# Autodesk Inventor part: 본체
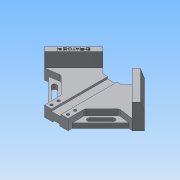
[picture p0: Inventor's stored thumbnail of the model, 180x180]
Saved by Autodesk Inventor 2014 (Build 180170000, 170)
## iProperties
Created: 2020-05
Part Number: 본체
Material: 알루미늄 6061
Document SubType Name: Modeling
Designer: net
Density: 2.71 g/cm^3
Appearance: 알루미늄 - 평지
Mass: 579.76 g
Surface Area: 409.973 cm^2
Volume: 213.934 cm^3
Author: net
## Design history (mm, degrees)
sketch "스케치1"
  geometry: L1 (0, 84.853)-(-84.853, 0); L2 (-84.853, 0)-(0, -84.853); L3 (0, -84.853)-(84.853, 0); L4 (84.853, 0)-(0, 84.853); L5 (-84.853, 0)-(84.853, 0); L6 (-35.355, 49.497)-(-16.005, 30.147); L7 (-16.005, 30.147)-(16.005, 30.147); L8 (16.005, 30.147)-(35.355, 49.497); L9 (0, 84.853)-(0, -84.853); L10 (-20, -64.853)-(20, -64.853); L11 (-6, 30.147)-(-6, -64.853); L12 (6, 30.147)-(6, -64.853); L13 (24.749, 38.891)-(74.246, -10.607); L14 (-24.749, 38.891)-(-74.246, -10.607); 3 further points
  constraints: 28 end point, 12 point on line, 10 perpendicular, 2 coincident, 2 parallel, 1 horizontal, 1 horizontal alignment, 1 midpoint, 1 vertical alignment
  dimensions: "d6" = 120 distance of L3.end L1.start; "d7" = 120 distance of L2.end L3.end (derived); "d9" = 50 distance of L1.start L6.start; "d10" = 50 distance of L8.end L1.start; "d11" = 20 distance from line of L2.end L10; "d13" = 12 distance between parallel lines of L12 L11; "d14" = 6 distance from line of L12 point (0, 0); "d15" = 15 distance between parallel lines of L4 L13; "d16" = 15 distance between parallel lines of L14 L1; "d69" = 95 distance of L12.start L12.end; "d70" = 40 distance of L10.start L10.end (derived)
extrude "돌출1" new body sketch "스케치1" distance "d17" = 42; taper "d18" = 0 deg
extrude "돌출2" join sketch "스케치1" distance "d19" = 18; taper "d20" = 0 deg
extrude "돌출4" cut sketch "스케치1" distance "d23" = 3; taper "d24" = 0 deg
sketch "스케치2"
  geometry: L1 (-20, -64.853)-(20, -64.853) reference; L2 (16.005, 30.147)-(-16.005, 30.147) reference; L3 (-8, 30.147)-(-8, -64.853); L4 (8, 30.147)-(8, -64.853); 1 further point
  constraints: 4 end point, 4 point on line, 2 perpendicular
  dimensions: "d25" = 16 distance between parallel lines of L4 L3; "d26" = 8 distance from line of L4 point (0, 0)
extrude "돌출5" cut sketch "스케치2" distance "d27" = 3.5; taper "d28" = 0 deg
sketch "스케치3"
  geometry: L1 (0, 42)-(0, 0) reference; L2 (15, 0)-(0, 0) reference; L3 (5, 0)-(0, 15); 1 further point
  constraints: 2 end point, 2 point on line
  dimensions: "d30" = 5 distance of L1.end L3.start; "d31" = 15 distance of L3.end L1.end
extrude "돌출6" cut sketch "스케치3" stored distance "d32" = 3.5; taper "d33" = 0 deg
sketch "스케치4"
  geometry: L1 (-74.246, -10.607)-(-20, -64.853) reference; L2 (-20, -64.853)-(-8, -64.853) reference; L3 (-74.246, -10.607)-(-49.497, -7.071); L4 (-49.497, -7.071)-(-20, -36.569); L5 (-20, -36.569)-(-20, -64.853); L6 (-84.853, 0)-(-35.355, 49.497) reference; L7 (-84.853, 0)-(-20, -64.853) reference; L8 (-49.497, -7.071)-(-63.64, -21.213); L9 (8, -64.853)-(-8, -64.853) reference; L10 (6, -64.853)-(20, -64.853) reference; 1 further point
  constraints: 8 end point, 2 perpendicular, 1 parallel, 1 point on line
  dimensions: "d34" = 20 distance between parallel lines of L4 L1; "d35" = 30 distance between parallel lines of L8 L6
extrude "돌출7" cut sketch "스케치4" stored distance "d36" = 10; taper "d37" = 0 deg
sketch "스케치5"
  geometry: L1 (-16.005, 30.147)-(-6, 30.147) reference; L2 (-6, 30.147)-(-6, -64.853) reference; L3 (-6, -64.853)-(-20, -64.853) reference; L4 (-20, -64.853)-(-20, -36.569) reference; L5 (-20, -36.569)-(-49.497, -7.071) reference; L6 (-49.497, -7.071)-(-74.246, -10.607) reference; L7 (-74.246, -10.607)-(-84.853, 0) reference; L8 (-84.853, 0)-(-35.355, 49.497) reference; L9 (-35.355, 49.497)-(-16.005, 30.147) reference; L10 (6, 30.147)-(16.005, 30.147) reference; L11 (16.005, 30.147)-(35.355, 49.497) reference; L12 (35.355, 49.497)-(84.853, 0) reference; L13 (84.853, 0)-(74.246, -10.607) reference; L14 (74.246, -10.607)-(49.497, -7.071) reference; L15 (49.497, -7.071)-(20, -36.569) reference; L16 (20, -36.569)-(20, -64.853) reference; L17 (20, -64.853)-(6, -64.853) reference; L18 (6, -64.853)-(6, 30.147) reference; L19 (-68.059, -9.723)-(-20, -57.782); L20 (-49.497, -18.385)-(-29.698, -38.184); L21 (-52.326, -21.213)-(-32.527, -41.012); L22 (-26.87, -35.355)-(-46.669, -15.556); L23 (-74.246, -10.607)-(-49.497, -7.071) reference; L24 (-49.497, -7.071)-(-20, -36.569) reference; L25 (-20, -36.569)-(-20, -64.853) reference; L26 (-68.059, -9.723)-(-49.497, -7.071); L27 (-20, -36.569)-(-20, -57.782); L28 (-20, -36.569)-(-49.497, -7.071); A1 r 4 centre (-49.497, -18.385) between (-46.669, -15.556) and (-52.326, -21.213); A2 r 4 centre (-29.698, -38.184) between (-32.527, -41.012) and (-26.87, -35.355); 2 further points
  constraints: 16 end point, 4 point on circle, 4 tangent, 3 collinear, 2 centre point, 2 parallel, 2 point on line, 1 midpoint, 1 perpendicular
  dimensions: "d38" = 5 distance between parallel lines of L19 L7; "d39" = 12 distance between parallel lines of L20 L7; "d40" = 8 distance between parallel lines of L22 L21; "d41" = 38 distance from line of L20.start L8; "d43" = 28 distance of L20.start L20.end
extrude "돌출8" join sketch "스케치5" distance "d44" = 8; taper "d45" = 0 deg
sketch "스케치6"
  geometry: L1 (-20, -36.569)-(-20, -64.853) reference; L2 (-20, -64.853)-(-8, -64.853) reference; C1 r 2.25 at (-14, -46.853); C2 r 2.25 at (-14, -58.853); 5 further points
  constraints: 2 centre point, 2 coincident, 2 horizontal alignment, 2 vertical alignment
  dimensions: "d46" = 12 distance of point (14, -58.853) point (14, -46.853); "d47" = 6 distance from line of L2 point (14, -58.853); "d48" = 28 distance of point (14, -58.853) point (-14, -58.853); "d49" = 6 distance from line of point (-14, -58.853) L1; "d50" = 4.5 diameter of C1; "d51" = 4.5 diameter of C2
extrude "돌출9" cut sketch "스케치6" distance "d52" = 8; taper "d53" = 0 deg
sketch "스케치7"
  geometry: L1 (20, -64.853)-(20, -57.782) reference; L2 (20, -64.853)-(6, -64.853) reference; C1 r 2.25 at (14, -58.853) reference; C2 r 4 at (14, -46.853); C3 r 4 at (14, -58.853); 5 further points
  constraints: 2 centre point, 2 coincident, 2 horizontal alignment, 2 vertical alignment
  dimensions: "d55" = 28 distance of point (14, -58.853) point (-14, -58.853); "d56" = 6 distance from line of L1 point (14, -58.853); "d57" = 6 distance from line of point (14, -58.853) L2; "d58" = 12 distance of point (14, -46.853) C1.centre; "d59" = 8 diameter of C2; "d60" = 8 diameter of C3
extrude "돌출10" cut sketch "스케치7" distance "d61" = 10; taper "d62" = 0 deg
sketch "스케치8"
  geometry: L1 (-74.246, -10.607)-(-24.749, 38.891) reference; L2 (-24.749, 38.891)-(-31.82, 45.962) reference; 2 further points
  constraints: 1 other
  dimensions: "d63" = 35 distance from line of L2 point (-53.033, 17.678); "d64" = 5 distance from line of L1 point (-53.033, 17.678)
feature "엠보싱1" sketch "스케치8" dims "d6" = 120, "d7" = 120 (derived), "d9" = 50, "d10" = 50, "d11" = 20, "d13" = 12, "d14" = 6, "d15" = 15, "d16" = 15, "d65" = 0.5, "d66" = 0, "d69" = 95, "d70" = 40 (derived)
fillet "모깎기1" dims "d67" = 5
fillet "모깎기2" dims "d68" = 5
node "솔리드1"
mirror "대칭1"
mirror "대칭2"
mirror "대칭3"
mirror "대칭4"
node "작업 평면1"
node "절단 모서리 투영1"
